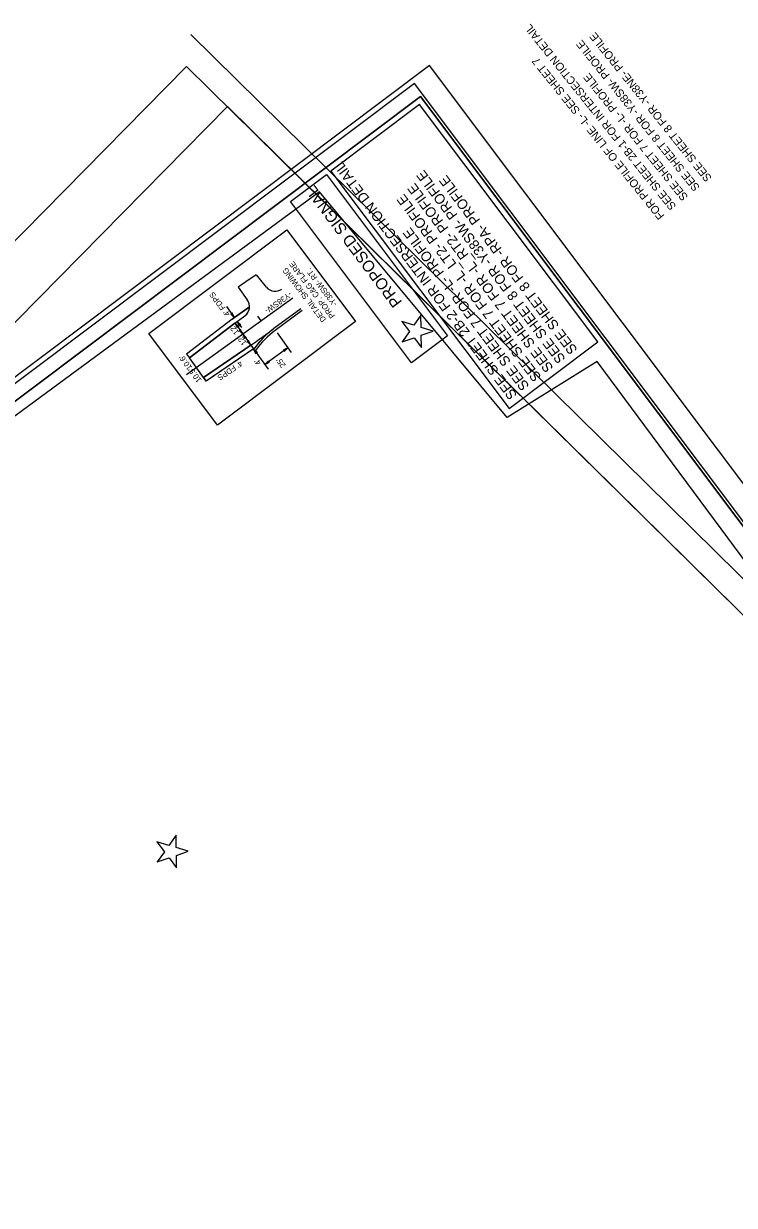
# Model space of a CAD drawing. Extents: x 1265100 to 1267089, y 771887 to 773927.
# Drawn here: x 1265722 to 1266344, y 772893 to 773927 of the extents above; entities that cross this region are included whole.
import ezdxf

# ---------------------------------------------------------------- set-up
doc = ezdxf.new("R2010")
doc.units = 0
for name, color, linetype in [('Exist DTM Regular Point Cogo Number', 7, 'Continuous'), ('Exist DTM Spot Elevation CELL', 7, 'Continuous'), ('Exist DTM Spot Elevation Cogo Number', 7, 'Continuous'), ('Exist Roads EOT', 7, 'Continuous'), ('Exist Utilities Other Pole Cogo Comment', 7, 'Continuous'), ('Exist Utilities Other Pole Cogo Number', 7, 'Continuous'), ('Exist Utilities Power Pole CELL', 7, 'Continuous'), ('Exist Utilities Power Pole Cogo Number', 7, 'Continuous'), ('Exist Utilities Power UG Cable SUE LOS B Cogo Point CELL', 7, 'Continuous'), ('Exist Utilities Sanitary Sewer Manhole CELL', 7, 'Continuous'), ('Exist Utilities Sanitary Sewer Manhole Cogo Number', 7, 'Continuous'), ('Exist Utilities Water Meter CELL', 7, 'Continuous'), ('Exist Utilities Water Meter Cogo Elevation', 7, 'Continuous'), ('Prop Conc 1ft 6in Curb and Gutter', 7, 'Continuous'), ('Prop Conc 4in Sidewalk', 7, 'Continuous'), ('Prop EOT', 7, 'Continuous'), ('Prop Horizontal Alignment Station Label', 7, 'Continuous'), ('Prop Plan Preparation Crest', 7, 'Continuous'), ('Prop Plan Preparation Watershed Post Construction', 7, 'Continuous'), ('Typical Terminator CELL', 7, 'Continuous')]:
    doc.layers.add(name, color=color, linetype=linetype)

msp = doc.modelspace()

# ---------------------------------------------------------------- linework, layer by layer
at = {"layer": 'Exist DTM Regular Point Cogo Number'}
for p, q in [((1265899.8, 773679.4), (1265906.8, 773669.7)), ((1265909.2, 773666.5), (1265913.1, 773661))]:
    msp.add_line(p, q, dxfattribs=at)
for points in [[(1265903.6, 773672.9), (1265906.8, 773669.7), (1265904.8, 773673.8), (1265904.5, 773672.9)], [(1265909.4, 773660.7), (1265907.4, 773664.8), (1265910.7, 773661.6), (1265909.7, 773661.6)], [(1265911.2, 773662.4), (1265909.2, 773666.5), (1265912.5, 773663.3), (1265911.5, 773663.3)], [(1265910.9, 773658.5), (1265914.2, 773655.3), (1265912.2, 773659.4), (1265911.9, 773658.5)], [(1265916.2, 773651.2), (1265914.2, 773655.3), (1265917.5, 773652.1), (1265916.5, 773652.1)], [(1265918, 773648.8), (1265921.2, 773645.6), (1265919.2, 773649.7), (1265918.9, 773648.8)], [(1265925.6, 773638.2), (1265923.6, 773642.3), (1265926.9, 773639.1), (1265925.9, 773639.1)], [(1265950.4, 773640), (1265953.6, 773643.3), (1265949.5, 773641.3), (1265950.4, 773641)], [(1265936.6, 773632), (1265933.4, 773628.7), (1265937.5, 773630.7), (1265936.6, 773631.1)]]:
    msp.add_lwpolyline(points, close=True, dxfattribs=at)
at = {"layer": 'Exist DTM Spot Elevation CELL'}
for points in [[(1266064, 773652.2), (1266070.6, 773643.5), (1266070.4, 773654.4), (1266080.7, 773657.9), (1266070.3, 773661.2), (1266070.1, 773672), (1266063.9, 773663.1), (1266053.4, 773666.3), (1266060, 773657.6), (1266053.7, 773648.7), (1266064, 773652.2)], [(1265849.6, 773197.1), (1265856.1, 773188.4), (1265856, 773199.3), (1265866.3, 773202.9), (1265855.9, 773206.1), (1265855.7, 773217), (1265849.4, 773208), (1265839, 773211.2), (1265845.6, 773202.5), (1265839.3, 773193.6), (1265849.6, 773197.1)]]:
    msp.add_lwpolyline(points, dxfattribs=at)
at = {"layer": 'Exist Roads EOT'}
for p, q in [((1265920, 773679.2), (1265904.8, 773668.3)), ((1265904.8, 773668.3), (1265865, 773637.9)), ((1265867.4, 773634.7), (1265907.2, 773665)), ((1265907.2, 773665), (1265915.9, 773671.3)), ((1265865, 773637.9), (1265867.4, 773634.7))]:
    msp.add_line(p, q, dxfattribs=at)
msp.add_lwpolyline([(1265921.2, 773645.6), (1265924.8, 773648.1), (1265927, 773649.7), (1265928.8, 773651.1), (1265930.4, 773652.1), (1265932.5, 773653.7), (1265933.6, 773654.5), (1265934.6, 773655.2), (1265935.5, 773655.9), (1265937.1, 773657), (1265938.2, 773657.8), (1265938.7, 773658.2), (1265939.1, 773658.4), (1265939.6, 773658.9), (1265939.9, 773659.1), (1265940, 773659.1), (1265940.2, 773659.2), (1265940.3, 773659.3), (1265940.3, 773659.3), (1265940.2, 773659.2), (1265940.1, 773659.1), (1265939.9, 773659), (1265939.7, 773658.8), (1265939.1, 773658.4), (1265938.8, 773658.1), (1265937.8, 773657.4), (1265936.8, 773656.5), (1265935.3, 773655.2), (1265934, 773654), (1265933.1, 773653.1), (1265931.2, 773651.3), (1265930.4, 773650.4), (1265930.1, 773650), (1265929.8, 773649.8), (1265929.2, 773649.1), (1265928.4, 773648.2), (1265927.2, 773646.8), (1265925.7, 773644.7), (1265924.1, 773642.7), (1265923.5, 773642.3), (1265882.1, 773614.2), (1265879.8, 773617.5)], close=True, dxfattribs=at)
msp.add_arc((1265910, 773679.4), 10, 305.8167, 358.9468, dxfattribs=at)
at = {"layer": 'Exist Utilities Other Pole Cogo Comment'}
msp.add_line((1265930.2, 773667), (1265927.3, 773671.1), dxfattribs=at)
at = {"layer": 'Exist Utilities Other Pole Cogo Number'}
for p, q in [((1265904.8, 773668.3), (1265920, 773679.2)), ((1265904.8, 773668.3), (1265865, 773637.9)), ((1265924.1, 773642.7), (1265882.1, 773614.2)), ((1265865, 773637.9), (1265867.4, 773634.7)), ((1265879.8, 773617.5), (1265882.1, 773614.2))]:
    msp.add_line(p, q, dxfattribs=at)
at = {"layer": 'Exist Utilities Power Pole CELL'}
for p, q in [((1265966.1, 773675.9), (1265942.6, 773658.5)), ((1265923.7, 773642), (1265925.3, 773640.9))]:
    msp.add_line(p, q, dxfattribs=at)
msp.add_arc((1265985.3, 773599.3), 73, 125.8167, 145.2881, dxfattribs=at)
at = {"layer": 'Exist Utilities Power UG Cable SUE LOS B Cogo Point CELL'}
msp.add_line((1265958, 773686.9), (1265865, 773619.8), dxfattribs=at)
at = {"layer": 'Exist Utilities Sanitary Sewer Manhole Cogo Number'}
for p, q in [((1265925.9, 773707.3), (1265934.7, 773696.5)), ((1265910, 773696.4), (1265918.1, 773685.3)), ((1265964.9, 773677.5), (1265941.4, 773660.1)), ((1265907.2, 773665), (1265867.4, 773634.7)), ((1265907.2, 773665), (1265915.9, 773671.3)), ((1265921.2, 773645.6), (1265879.8, 773617.5)), ((1265879.8, 773617.5), (1265867.4, 773634.7))]:
    msp.add_line(p, q, dxfattribs=at)
msp.add_lwpolyline([(1265925.9, 773707.3), (1265916.7, 773701), (1265910, 773696.4)], dxfattribs=at)
for centre, radius, start, end in [((1265942.5, 773702.8), 10, 219.3843, 305.8167), ((1265910, 773679.4), 10, 305.8167, 35.98), ((1265985.3, 773599.3), 75, 125.8167, 145.2881)]:
    msp.add_arc(centre, radius, start, end, dxfattribs=at)
at = {"layer": 'Exist Utilities Water Meter CELL'}
for p, q in [((1265907.4, 773664.8), (1265921.2, 773645.6)), ((1265944.1, 773656.5), (1265956.5, 773639.3)), ((1265921.2, 773645.6), (1265936.3, 773624.7)), ((1265953.6, 773643.3), (1265933.4, 773628.7))]:
    msp.add_line(p, q, dxfattribs=at)
msp.add_lwpolyline([(1265892, 773575.6), (1265831.8, 773655.8), (1265952.7, 773746.6), (1266012.9, 773666.4)], close=True, dxfattribs=at)
at = {"layer": 'Exist Utilities Water Meter Cogo Elevation'}
msp.add_lwpolyline([(1266061.8, 773630.1), (1265955.8, 773771.3), (1265987.3, 773794.9), (1266093.3, 773653.7)], close=True, dxfattribs=at)
at = {"layer": 'Prop Conc 1ft 6in Curb and Gutter'}
for points in [[(1265230.2, 773232.7), (1266131, 772033.2), (1266970.6, 772663.8), (1266069.8, 773863.2)], [(1266970.6, 772663.8), (1266131, 772033.2), (1265350.4, 773072.7), (1265470.3, 773162.8), (1265350.2, 773322.8), (1266069.8, 773863.2)], [(1266224.9, 773648.5), (1266068.9, 773856.2), (1265991.3, 773797.9), (1266147.3, 773590.2)]]:
    msp.add_lwpolyline(points, close=True, dxfattribs=at)
at = {"layer": 'Prop Conc 4in Sidewalk'}
msp.add_line((1267067.9, 772735.9), (1265868.7, 773917.4), dxfattribs=at)
at = {"layer": 'Prop EOT'}
msp.add_lwpolyline([(1267064.8, 772542.5), (1266064.3, 773874.7), (1265220.7, 773241.2), (1266221.2, 771909)], close=True, dxfattribs=at)
at = {"layer": 'Prop Horizontal Alignment Station Label'}
msp.add_lwpolyline([(1267088.6, 772544.2), (1266077.6, 773890.3), (1265202.1, 773232.8), (1266213, 771886.6)], close=True, dxfattribs=at)
at = {"layer": 'Prop Plan Preparation Crest'}
msp.add_lwpolyline([(1266196.5, 772088.8), (1266933.5, 772836.7), (1265865, 773889.5), (1265276.5, 773292.2), (1265446.9, 773124.3), (1265298.5, 772973.6)], close=True, dxfattribs=at)
at = {"layer": 'Prop Plan Preparation Watershed Post Construction'}
msp.add_lwpolyline([(1266897.8, 772871.8), (1265900.6, 773854.4), (1265312.1, 773257.1), (1265446.9, 773124.3), (1265298.5, 772973.6), (1266160.9, 772123.8)], close=True, dxfattribs=at)
at = {"layer": 'Typical Terminator CELL'}
msp.add_lwpolyline([(1266289.4, 772153.6), (1266298.1, 772160.4), (1266307.8, 772184.2), (1266331.9, 772215.3), (1266332.4, 772261.5), (1266387.5, 772467.5), (1266710.2, 772749.1), (1266813.6, 772836.4), (1266224.3, 773631.5), (1266145.6, 773582.4), (1265981.3, 773779.7), (1265375.9, 773334.6), (1265484.1, 773191.1), (1265496.2, 773177.8), (1265369, 773080.5), (1265370.5, 773071.5), (1265889, 772374.4), (1265992.8, 772219.7), (1266130.5, 772035.9)], close=True, dxfattribs=at)

# ---------------------------------------------------------------- texts
at = {"layer": 'Exist DTM Spot Elevation Cogo Number'}
msp.add_text('PROPOSED SIGNAL', height=10, rotation=126.9057, dxfattribs=at).set_placement((1266054, 773683.4))
at = {"layer": 'Exist Utilities Power Pole Cogo Number'}
for s, p in [('SEE SHEET 2B-2 FOR INTERSECTION DETAIL', (1266154.7, 773602.1)), ('SEE SHEET 8 FOR -Y38SW- PROFILE', (1266197, 773633.8)), ('SEE SHEET 7 FOR -L_RT2- PROFILE', (1266186.4, 773625.9)), ('SEE SHEET 8 FOR -RPA- PROFILE', (1266207.5, 773641.7)), ('SEE SHEET 7 FOR -L_LT2- PROFILE', (1266175.8, 773617.9)), ('SEE SHEET 7 FOR -L- PROFILE', (1266165.3, 773610))]:
    msp.add_text(s, height=8.75, rotation=126.9057, dxfattribs=at).set_placement(p)
at = {"layer": 'Exist Utilities Sanitary Sewer Manhole CELL'}
for s, p in [('SEE SHEET 2B-1 FOR INTERSECTION DETAIL', (1266293.9, 773767.3)), ('SEE SHEET 8 FOR -Y38SW- PROFILE', (1266314.6, 773783.8)), ('SEE SHEET 8 FOR -Y38NE- PROFILE', (1266325, 773792.1)), ('FOR PROFILE OF LINE -L- SEE SHEET 7', (1266283.6, 773759)), ('SEE SHEET 7 FOR -L- PROFILE', (1266304.3, 773775.5))]:
    msp.add_text(s, height=7, rotation=128.7, dxfattribs=at).set_placement(p)
at = {"layer": 'Exist Utilities Water Meter CELL'}
for s, rotation, p in [('PROP. C&G FLARE', 127.34, (1265995.1, 773671.4)), ('DETAIL SHOWING', 127.34, (1265987.4, 773668.1)), ('-Y38SW- RT.', 127.34, (1265997.3, 773681.9)), ("4' FDPS", 127.34, (1265903.4, 773673.1)), ('-Y38SW-', 215.8147, (1265954.9, 773692.9)), ("12'", 125.8167, (1265911.2, 773656.9)), ("12'", 125.8167, (1265918, 773647.6)), ("10.6'", 125.8167, (1265870.2, 773626.1)), ("4'", 125.8167, (1265930.6, 773630.2)), ("25'", 125.8167, (1265952, 773628.1)), ("10.5'", 125.8167, (1265878.4, 773615.1)), ("4' FDPS", 213.651, (1265911.9, 773632.3))]:
    msp.add_text(s, height=5, rotation=rotation, dxfattribs=at).set_placement(p)

doc.saveas('drawing.dxf')
